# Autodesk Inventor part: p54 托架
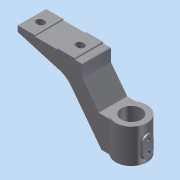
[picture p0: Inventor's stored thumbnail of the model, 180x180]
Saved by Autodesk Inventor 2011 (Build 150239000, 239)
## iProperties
Created: 2014-01
Part Number: p54 托架
Document SubType Name: Modeling
Designer: Administrator
Density: 1 g/cm^3
Author: Administrator
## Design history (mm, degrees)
sketch "草图1"
  geometry: C1 r 27.5 at (0, 0); 1 further point
  constraints: 1 centre point, 1 coincident
  dimensions: "d0" = 55 diameter of C1
extrude "拉伸1" new body sketch "草图1" distance "d1" = 60; taper "d2" = 0 deg
hole "Hole1" diameter "d5" = 35; stored, may be unused: countersink angle "d9" = 90 deg, drill point angle "d11" = 118 deg; dims "d3" = 10, "d4" = 10, "d6" = 6, "d7" = 4, "d8" = 2, "d10" = 35
chamfer "倒角1" distance "d12" = 1; stored, may be unused: second distance "d13" = 2, angle "d14" = 45 deg
node "工作平面1"
sketch "草图2"
  geometry: L1 (-27.5, 60)-(27.5, 60) reference; L2 (-27.5, 0)-(27.5, 0) reference; L3 (-27.5, 0)-(-27.5, 60) reference; L4 (27.5, 0)-(27.5, 60) reference; L5 (0, 44)-(9, 44); L6 (9, 35)-(9, 15); L7 (9, 6)-(0, 6); L8 (-9, 15)-(-9, 44); A1 r 9 centre (0, 15) between (-9, 15) and (9, 15); A2 r 9 centre (0, 35) between (9, 35) and (-9, 35); 3 further points
  constraints: 8 end point, 6 point on circle, 2 centre point, 2 parallel, 1 horizontal, 1 midpoint, 1 perpendicular, 1 point on line, 1 vertical alignment
  dimensions: "d16" = 18 distance of L8.end L5.end; "d17" = 38 distance of L5.end L7.start; "d21" = 18 diameter of A1; "d22" = 18 diameter of A2
extrude "拉伸2" join sketch "草图2" stored distance "d23" = 60; taper "d24" = 0 deg
hole "Hole2" diameter "d27" = 6.647; stored, may be unused: countersink angle "d31" = 90 deg, drill point angle "d33" = 118 deg; dims "d25" = 10, "d26" = 10, "d28" = 12, "d29" = 4, "d30" = 2, "d32" = 20
hole "Hole3" diameter "d36" = 6.647; stored, may be unused: countersink angle "d40" = 90 deg, drill point angle "d42" = 118 deg; dims "d34" = 10, "d35" = 10, "d37" = 13, "d38" = 4, "d39" = 2, "d41" = 20
node "工作平面2"
sketch "草图3"
  geometry: L1 (-175, 25)-(-61, 25); L2 (-61, 25)-(-61, -25); L3 (-61, -25)-(-175, -25); L4 (-175, -25)-(-175, 25); C1 r 17.5 at (0, 0) reference; C2 r 27.5 at (0, 0) reference; 2 further points
  constraints: 8 end point, 2 parallel, 1 horizontal, 1 horizontal alignment, 1 midpoint, 1 perpendicular
  dimensions: "d44" = 114 distance of L1.start L1.end; "d45" = 50 distance of L3.end L1.start; "d46" = 175 distance from line of point (0, 0) L4
extrude "拉伸3" join sketch "草图3" distance "d47" = 10; taper "d48" = 0 deg
sketch "草图4"
  geometry: L1 (-175, -25)-(-175, 25) reference; L2 (-61, 25)-(-61, -25) reference; L3 (-145, 25)-(-105, 25); L4 (-105, 25)-(-105, -25); L5 (-105, -25)-(-145, -25); L6 (-145, -25)-(-145, 25); L7 (-75, 25)-(-61, 25); L8 (-61, 25)-(-61, -25); L9 (-61, -25)-(-75, -25); L10 (-75, -25)-(-75, 25); 4 further points
  constraints: 16 end point, 4 midpoint, 4 parallel, 2 horizontal, 2 perpendicular, 1 horizontal alignment
  dimensions: "d49" = 40 distance of L3.start L3.end; "d50" = 50 distance of L5.end L3.start; "d51" = 30 distance between parallel lines of L6 L1; "d52" = 14 distance of L7.start L7.end; "d53" = 50 distance of L7.end L8.end
extrude "拉伸4" cut sketch "草图4" distance "d54" = 2; taper "d55" = 0 deg
sketch "草图5"
  geometry: L1 (-161.905, 5.986)-(-158.524, 6); L2 (-161.315, -5.997)-(-158.315, -5.997); A1 r 6 centre (-158.5, 0) between (-158.685, -5.997) and (-158.524, 6); A2 r 6 centre (-161.5, 0) between (-161.143, 5.989) and (-161.315, -5.997); 1 further point
  constraints: 6 point on circle, 4 end point, 2 centre point, 2 point on line, 1 tangent
  dimensions: "d59" = 12 diameter of A1; "d60" = 12 diameter of A2
extrude "拉伸5" cut sketch "草图5" stored distance "d61" = 2; taper "d62" = 0 deg
node "工作平面3"
mirror "镜像1"
node "工作平面4"
sketch "草图7"
  geometry: L1 (145, 118)-(145, 120) reference; L2 (145, 120)-(175, 120) reference; L3 (175, 120)-(175, 110) reference; L4 (175, 110)-(61, 110) reference; L5 (61, 118)-(61, 110) reference; L6 (61, 118)-(75, 118) reference; L7 (75, 118)-(75, 120) reference; L8 (75, 120)-(105, 120) reference; L9 (105, 120)-(105, 118) reference; L10 (105, 118)-(145, 118) reference; L11 (-17.5, 60)-(17.5, 60) reference; L12 (27.5, 0)-(27.5, 60) reference; L13 (-27.5, 60)-(27.5, 60) reference; L14 (-27.5, 0)-(27.5, 0) reference; L15 (17.5, 1)-(17.5, 60) reference; L16 (175, 110)-(101.697, 88.691); L17 (27.5, 4)-(17.5, 4); L18 (32.148, 58)-(17.5, 58); L19 (81.004, 74.469)-(27.5, 4); L20 (61, 110)-(61, 96); L21 (61, 96)-(32.148, 58); L22 (17.5, 4)-(5.787, 4); L23 (5.787, 4)-(5.787, 58); L24 (5.787, 58)-(17.5, 58); L25 (11.643, 58)-(5.787, 58); L26 (5.787, 4)-(11.643, 4); A1 r 40 centre (112.862, 50.281) between (101.697, 88.691) and (81.004, 74.469); 1 further point
  constraints: 22 end point, 3 parallel, 3 perpendicular, 3 point on line, 2 collinear, 2 midpoint, 2 point on circle, 2 tangent, 1 centre point
  dimensions: "d68" = 4 distance between parallel lines of L14 L17; "d69" = 2 distance between parallel lines of L13 L18; "d70" = 40 radius of A1; "d71" = 14 distance of L4.end L20.end
extrude "拉伸6" join sketch "草图7" distance "d72" = 7; taper "d73" = 0 deg
mirror "镜像2"
sketch "草图8"
  geometry: L1 (61, 96)-(61, 110) reference; L2 (32.148, 58)-(61, 96) reference; L3 (20.791, 58)-(32.148, 58) reference; L4 (27.5, 0)-(27.5, 60) reference; L5 (175, 110)-(61, 110) reference; L6 (69, 110)-(69, 92.979); L7 (17.5, 1)-(17.5, 60) reference; L8 (69, 92.979)-(27.5, 38.321); L9 (69, 110)-(61, 110); L10 (61, 96)-(32.148, 58); L11 (61, 96)-(32.148, 58) reference; L12 (32.148, 58)-(27.5, 58); L13 (27.5, 38.321)-(27.5, 58); L14 (-27.5, 60)-(27.5, 60) reference; 1 further point
  constraints: 12 end point, 4 point on line, 2 collinear, 2 perpendicular, 1 parallel
  dimensions: "d74" = 8 distance between parallel lines of L1 L6
extrude "拉伸7" join sketch "草图8" stored distance "d75" = 36; taper "d76" = 0 deg
sketch "草图10"
  geometry: L1 (17.5, 58)-(17.5, 4) reference; L2 (-17.5, 60)-(17.5, 60) reference; L3 (17.5, 58)-(2.316, 58); L4 (2.316, 58)-(2.316, 4); L5 (2.316, 4)-(17.5, 4); 1 further point
  constraints: 6 end point, 2 perpendicular, 1 parallel
extrude "拉伸9" join sketch "草图10" distance "d79" = 4; taper "d80" = 0 deg
sketch "草图11"
  geometry: L1 (27.5, 0)-(27.5, 60) reference; L2 (20.791, 4)-(20.791, 58) reference; L3 (27.5, 58)-(20.791, 58); L4 (20.791, 58)-(27.5, 58) reference; L5 (20.791, 4)-(27.5, 4); L6 (27.5, 4)-(20.791, 4) reference; 1 further point
  constraints: 4 end point, 2 collinear, 1 point on line
extrude "拉伸10" join sketch "草图11" distance "d81" = 50; taper "d82" = 0 deg
mirror "镜像3"
mirror "镜像4"
fillet "圆角1" dims "d83" = 2
fillet "圆角2" dims "d84" = 2
node "实体1"
node "投影回路1"
node "投影回路2"
node "投影回路3"
other parameters: "d18" = 9, "d19" = 9, "d20" = 15, "d57" = 1.5, "d63" = -125, "d64" = -25
